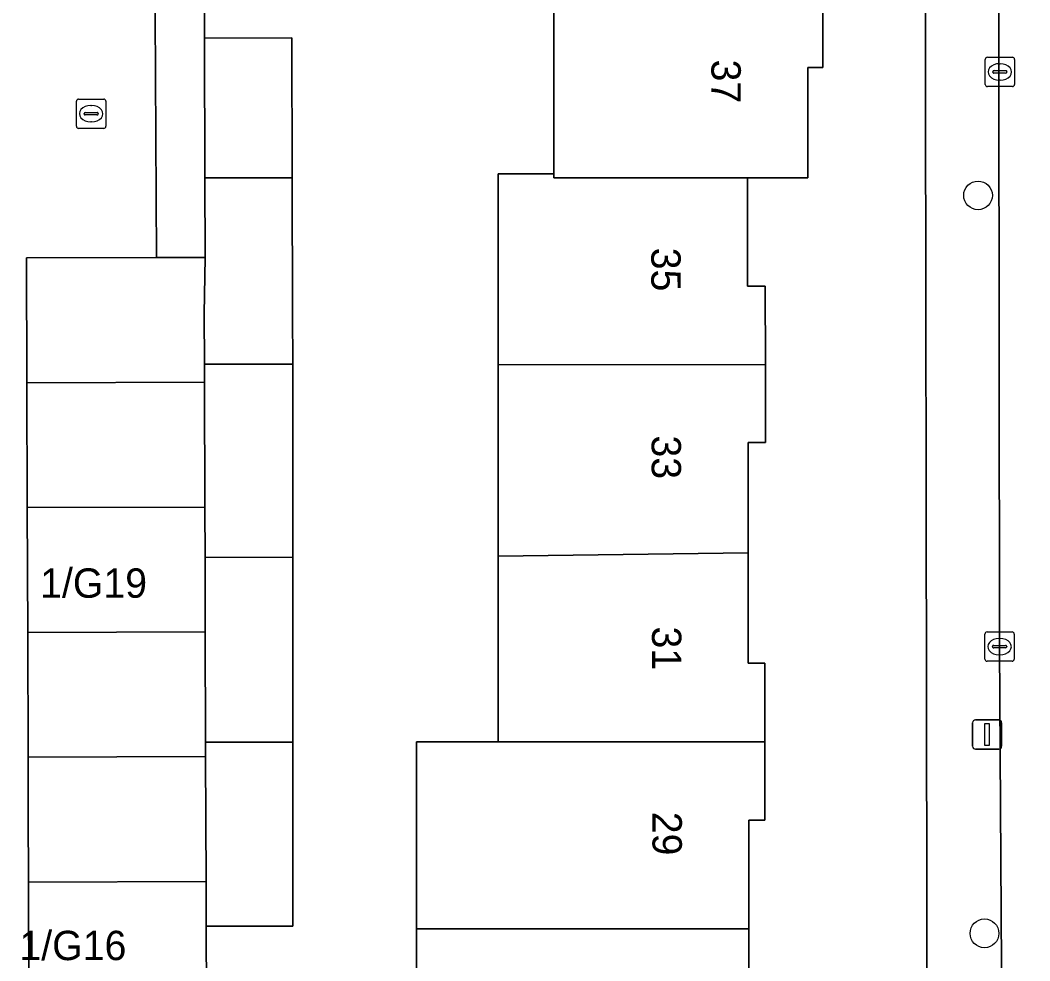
# Model space of a CAD drawing. Extents: x 160732 to 162107, y 387428 to 388479.
# Drawn here: x 161123.16 to 161157.55, y 387994.94 to 388026.99 of the extents above; entities that cross this region are included whole.
import ezdxf

# ---------------------------------------------------------------- set-up
doc = ezdxf.new("R2010")
doc.units = 0
for name, color, linetype in [('IMGEO_Boom', 7, 'Continuous'), ('IMGEO_Erf', 7, 'Continuous'), ('IMGEO_Kolk', 7, 'Continuous'), ('IMGEO_Lichtmast', 7, 'Continuous'), ('IMGEO_Pand', 7, 'Continuous'), ('IMGEO_Pand_nummerreeks', 7, 'Continuous'), ('IMGEO_Rijbaan_lokaal_open', 7, 'Continuous'), ('IMGEO_Voetpad_open', 7, 'Continuous')]:
    doc.layers.add(name, color=color, linetype=linetype)

msp = doc.modelspace()

# ---------------------------------------------------------------- linework, layer by layer
at = {"layer": 'IMGEO_Boom'}
for centre in [(161155.787, 388021.019), (161156.006, 387995.878)]:
    msp.add_circle(centre, 0.489, dxfattribs=at)
at = {"layer": 'IMGEO_Erf'}
for points in [[(161154.07, 387983.142), (161153.967, 388045.181)], [(161129.46, 388029.837), (161129.438, 388026.38), (161132.413, 388026.39), (161132.427, 388021.616), (161132.441, 388016.997), (161132.442, 388015.268), (161132.442, 388008.691), (161132.442, 388002.389), (161132.442, 387996.127), (161129.495, 387996.124), (161129.503, 387993.682)], [(161139.44, 388008.728), (161139.44, 388015.252), (161139.439, 388016.751), (161139.438, 388021.75), (161141.339, 388021.75), (161141.337, 388028.062)], [(161150.504, 388028.062), (161150.505, 388025.374), (161149.99, 388025.373), (161149.991, 388021.615), (161147.932, 388021.614), (161147.933, 388017.923), (161148.541, 388017.924), (161148.542, 388015.26), (161148.543, 388012.596), (161147.958, 388012.596), (161147.959, 388008.838), (161147.96, 388005.078), (161148.519, 388005.079), (161148.52, 388002.408), (161148.52, 388000), (161148.52, 387999.735), (161147.979, 387999.735), (161147.98, 387996.03), (161147.981, 387992.327)], [(161136.66, 387989.652), (161136.66, 387996.03), (161136.66, 388002.408), (161139.44, 388002.408), (161139.44, 388008.728)]]:
    msp.add_lwpolyline(points, dxfattribs=at)
at = {"layer": 'IMGEO_Kolk'}
for p, q in [((161156.03, 388024.8), (161156.03, 388025.652)), ((161156.105, 388025.726), (161156.957, 388025.726)), ((161157.031, 388025.652), (161157.031, 388024.8)), ((161156.289, 388025.22), (161156.289, 388025.232)), ((161156.332, 388025.269), (161156.73, 388025.269)), ((161156.518, 388025.506), (161156.543, 388025.506)), ((161156.773, 388025.232), (161156.773, 388025.22)), ((161156.727, 388025.183), (161156.329, 388025.183)), ((161156.541, 388024.946), (161156.516, 388024.946)), ((161156.957, 388024.726), (161156.105, 388024.726)), ((161125.077, 388023.376), (161125.077, 388024.228)), ((161125.152, 388024.302), (161126.004, 388024.302)), ((161126.078, 388024.228), (161126.078, 388023.376)), ((161125.379, 388023.845), (161125.777, 388023.845)), ((161125.565, 388024.082), (161125.59, 388024.082)), ((161125.336, 388023.796), (161125.336, 388023.808)), ((161125.774, 388023.759), (161125.376, 388023.759)), ((161125.588, 388023.522), (161125.563, 388023.522)), ((161125.82, 388023.808), (161125.82, 388023.796)), ((161126.004, 388023.302), (161125.152, 388023.302)), ((161156.02, 388005.221), (161156.02, 388006.073)), ((161156.095, 388006.147), (161156.947, 388006.147)), ((161157.021, 388006.073), (161157.021, 388005.221)), ((161156.279, 388005.641), (161156.279, 388005.653)), ((161156.322, 388005.69), (161156.72, 388005.69)), ((161156.508, 388005.927), (161156.533, 388005.927)), ((161156.763, 388005.653), (161156.763, 388005.641)), ((161156.717, 388005.604), (161156.319, 388005.604)), ((161156.531, 388005.367), (161156.506, 388005.367)), ((161156.947, 388005.147), (161156.095, 388005.147))]:
    msp.add_line(p, q, dxfattribs=at)
for points in [[(161156.03, 388024.8), (161156.03, 388025.652)], [(161156.105, 388025.726), (161156.957, 388025.726)], [(161157.031, 388025.652), (161157.031, 388024.8)], [(161156.957, 388024.726), (161156.105, 388024.726)], [(161125.077, 388023.376), (161125.077, 388024.228)], [(161125.152, 388024.302), (161126.004, 388024.302)], [(161126.078, 388024.228), (161126.078, 388023.376)], [(161126.004, 388023.302), (161125.152, 388023.302)], [(161156.02, 388005.221), (161156.02, 388006.073)], [(161156.095, 388006.147), (161156.947, 388006.147)], [(161157.021, 388006.073), (161157.021, 388005.221)], [(161156.947, 388005.147), (161156.095, 388005.147)]]:
    msp.add_lwpolyline(points, dxfattribs=at)
for centre, radius, start, end in [((161156.107, 388025.65), 0.0765, 91.552, 178.448), ((161156.107, 388025.65), 0.0765, 91.552, 178.448), ((161156.955, 388025.65), 0.0765, 1.552, 88.448), ((161156.955, 388025.65), 0.0765, 1.552, 88.448), ((161156.329, 388025.229), 0.0403, 85.8775, 175.7526), ((161156.326, 388025.219), 0.0366, 178.938, 274.7102), ((161156.73, 388025.226), 0.043, 264.8664, 352.4533), ((161156.734, 388025.231), 0.0386, 1.7309, 96.639), ((161156.107, 388024.802), 0.0765, 181.552, 268.448), ((161156.107, 388024.802), 0.0765, 181.552, 268.448), ((161156.955, 388024.802), 0.0765, 271.552, 358.448), ((161156.955, 388024.802), 0.0765, 271.552, 358.448), ((161125.154, 388024.226), 0.0765, 91.552, 178.448), ((161125.154, 388024.226), 0.0765, 91.552, 178.448), ((161126.002, 388024.226), 0.0765, 1.552, 88.448), ((161126.002, 388024.226), 0.0765, 1.552, 88.448), ((161125.376, 388023.805), 0.0403, 85.8775, 175.7526), ((161125.781, 388023.807), 0.0386, 1.7309, 96.639), ((161125.373, 388023.795), 0.0366, 178.938, 274.7102), ((161125.777, 388023.802), 0.043, 264.8664, 352.4533), ((161125.154, 388023.378), 0.0765, 181.552, 268.448), ((161125.154, 388023.378), 0.0765, 181.552, 268.448), ((161126.002, 388023.378), 0.0765, 271.552, 358.448), ((161126.002, 388023.378), 0.0765, 271.552, 358.448), ((161156.097, 388006.071), 0.0765, 91.552, 178.448), ((161156.097, 388006.071), 0.0765, 91.552, 178.448), ((161156.945, 388006.071), 0.0765, 1.552, 88.448), ((161156.945, 388006.071), 0.0765, 1.552, 88.448), ((161156.319, 388005.65), 0.0403, 85.8775, 175.7526), ((161156.316, 388005.64), 0.0366, 178.938, 274.7102), ((161156.72, 388005.647), 0.043, 264.8664, 352.4533), ((161156.724, 388005.652), 0.0386, 1.7309, 96.639), ((161156.097, 388005.223), 0.0765, 181.552, 268.448), ((161156.097, 388005.223), 0.0765, 181.552, 268.448), ((161156.945, 388005.223), 0.0765, 271.552, 358.448), ((161156.945, 388005.223), 0.0765, 271.552, 358.448)]:
    msp.add_arc(centre, radius, start, end, dxfattribs=at)
for centre, major_axis, ratio, start_param, end_param in [((161156.517, 388025.226), (-0.387, 0.002), 0.722429, 4.712389, 7.853982), ((161156.542, 388025.226), (-0.39, 0.002), 0.717154, 1.570796, 4.712389), ((161125.564, 388023.802), (-0.387, 0.002), 0.722429, 4.712389, 7.853982), ((161125.589, 388023.802), (-0.39, 0.002), 0.717154, 1.570796, 4.712389), ((161156.507, 388005.647), (-0.387, 0.002), 0.722429, 4.712389, 7.853982), ((161156.532, 388005.647), (-0.39, 0.002), 0.717154, 1.570796, 4.712389)]:
    msp.add_ellipse(centre, major_axis=major_axis, ratio=ratio, start_param=start_param, end_param=end_param, dxfattribs=at)
at = {"layer": 'IMGEO_Lichtmast'}
for p, q in [((161155.601, 388002.252), (161155.601, 388003.052)), ((161155.601, 388003.052), (161155.601, 388002.252)), ((161155.701, 388003.152), (161156.491, 388003.152)), ((161156.491, 388003.152), (161155.701, 388003.152)), ((161156.591, 388003.052), (161156.591, 388002.252)), ((161156.591, 388002.252), (161156.591, 388003.052)), ((161156.491, 388002.152), (161155.701, 388002.152)), ((161155.701, 388002.152), (161156.491, 388002.152))]:
    msp.add_line(p, q, dxfattribs=at)
msp.add_lwpolyline([(161156.021, 388003.027), (161156.171, 388003.027), (161156.171, 388002.277), (161156.021, 388002.277), (161156.021, 388003.027)], dxfattribs=at)
for centre, start, end in [((161155.701, 388003.052), 90, 180), ((161155.701, 388003.052), 90, 180), ((161156.491, 388003.052), 0, 90), ((161156.491, 388003.052), 360, 90), ((161155.701, 388002.252), 180, 270), ((161155.701, 388002.252), 180, 270), ((161156.491, 388002.252), 270, 0), ((161156.491, 388002.252), 270, 0)]:
    msp.add_arc(centre, 0.1, start, end, dxfattribs=at)
at = {"layer": 'IMGEO_Pand'}
for points in [[(161147.932, 388021.614), (161149.991, 388021.615), (161149.99, 388025.373), (161150.505, 388025.374), (161150.504, 388028.062), (161141.337, 388028.062), (161141.339, 388021.75), (161141.34, 388021.615)], [(161129.452, 388021.617), (161132.427, 388021.616), (161132.413, 388026.39), (161129.438, 388026.38)], [(161132.427, 388021.616), (161129.452, 388021.617), (161129.46, 388018.905), (161129.43, 388016.988), (161129.435, 388015.266), (161132.442, 388015.268), (161132.441, 388016.997)], [(161141.34, 388021.615), (161141.339, 388021.75), (161139.438, 388021.75), (161139.439, 388016.751), (161139.44, 388015.252), (161148.542, 388015.26), (161148.541, 388017.924), (161147.933, 388017.923), (161147.932, 388021.614)], [(161129.46, 388018.905), (161127.799, 388018.9), (161123.375, 388018.887), (161123.388, 388014.635), (161129.437, 388014.654), (161129.435, 388015.266), (161129.43, 388016.988)], [(161132.442, 388015.268), (161129.435, 388015.266), (161129.437, 388014.654), (161129.451, 388010.402), (161129.456, 388008.688), (161132.442, 388008.691)], [(161147.959, 388008.838), (161147.958, 388012.596), (161148.543, 388012.596), (161148.542, 388015.26), (161139.44, 388015.252), (161139.44, 388008.728)], [(161123.402, 388010.383), (161129.451, 388010.402), (161129.437, 388014.654), (161123.388, 388014.635)], [(161129.456, 388008.688), (161129.451, 388010.402), (161123.402, 388010.383), (161123.415, 388006.131), (161129.464, 388006.15)], [(161148.52, 388002.408), (161148.519, 388005.079), (161147.96, 388005.078), (161147.959, 388008.838), (161139.44, 388008.728), (161139.44, 388002.408)], [(161132.442, 388008.691), (161129.456, 388008.688), (161129.464, 388006.15), (161129.476, 388002.386), (161132.442, 388002.389)], [(161129.464, 388006.15), (161123.415, 388006.131), (161123.428, 388001.879), (161129.477, 388001.898), (161129.476, 388002.386)], [(161132.442, 388002.389), (161129.476, 388002.386), (161129.477, 388001.898), (161129.49, 387997.644), (161129.495, 387996.124), (161132.442, 387996.127)], [(161147.979, 387999.735), (161148.52, 387999.735), (161148.52, 388000), (161148.52, 388002.408), (161139.44, 388002.408), (161136.66, 388002.408), (161136.66, 387996.03), (161139.444, 387996.03), (161147.98, 387996.03)], [(161129.477, 388001.898), (161123.428, 388001.879), (161123.434, 388000), (161123.441, 387997.627), (161129.49, 387997.644)], [(161129.495, 387996.124), (161129.49, 387997.644), (161123.441, 387997.627), (161123.451, 387993.664), (161129.313, 387993.681), (161129.503, 387993.682)], [(161136.66, 387989.652), (161148.53, 387989.652), (161148.53, 387992.328), (161147.981, 387992.327), (161147.98, 387996.03), (161139.444, 387996.03), (161136.66, 387996.03)]]:
    msp.add_lwpolyline(points, close=True, dxfattribs=at)
at = {"layer": 'IMGEO_Rijbaan_lokaal_open'}
msp.add_lwpolyline([(161123.451, 387993.664), (161123.441, 387997.627), (161123.434, 388000), (161123.428, 388001.879), (161123.415, 388006.131), (161123.402, 388010.383), (161123.388, 388014.635), (161123.375, 388018.887), (161127.799, 388018.9), (161127.738, 388031.317), (161127.725, 388037.62), (161127.744, 388048.8), (161122.971, 388048.812)], dxfattribs=at)
for points in [[(161156.469, 388045.652), (161156.521, 388005.647), (161156.651, 387983.882), (161156.61, 387976.781), (161156.629, 387968.165), (161161.565, 387968.157), (161161.475, 388044.985), (161161.475, 388045.161), (161161.493, 388045.766)], [(161129.438, 388026.38), (161129.46, 388029.837), (161129.453, 388031.325), (161127.738, 388031.317), (161127.799, 388018.9), (161129.46, 388018.905), (161129.452, 388021.617)]]:
    msp.add_lwpolyline(points, close=True, dxfattribs=at)
at = {"layer": 'IMGEO_Voetpad_open'}
for points in [[(161156.595, 387957.722), (161156.629, 387968.165), (161156.61, 387976.781), (161155.524, 387976.799), (161155.53, 387983.877), (161156.651, 387983.882), (161156.521, 388005.647), (161156.469, 388045.652)], [(161153.967, 388045.181), (161154.07, 387983.142), (161154.072, 387981.627), (161154.078, 387978.287), (161154.064, 387969.974), (161154.063, 387960.237), (161155.651, 387955.623)]]:
    msp.add_lwpolyline(points, dxfattribs=at)

# ---------------------------------------------------------------- texts
at = {"layer": 'IMGEO_Pand_nummerreeks'}
for s, rotation, p in [('37', 270.0915, (161146.704, 388025.646)), ('35', 270.1075, (161144.656, 388019.236)), ('33', 270.1075, (161144.668, 388012.84)), ('31', 270.1075, (161144.68, 388006.331)), ('29', 269.9998, (161144.698, 388000.02))]:
    msp.add_text(s, height=1, rotation=rotation, dxfattribs=at).set_placement(p)
for s, p in [('1/G19', (161123.839, 388007.312)), ('1/G16', (161123.135, 387994.966))]:
    msp.add_text(s, height=1, dxfattribs=at).set_placement(p)

doc.saveas('drawing.dxf')
